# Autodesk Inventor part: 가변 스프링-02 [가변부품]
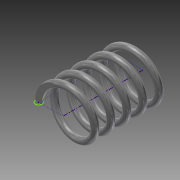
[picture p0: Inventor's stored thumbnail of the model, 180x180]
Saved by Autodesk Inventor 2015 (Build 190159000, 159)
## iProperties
Created: 2015-05
Part Number: 가변 스프링-02 [가변부품]
Material: 강철, 탄소
Document SubType Name: Modeling
Designer: Young-Hwan
Density: 7.85 g/cm^3
Appearance: 반연마
Mass: 18.8381 g
Surface Area: 32.5478 cm^2
Volume: 2.39976 cm^3
Author: Young-Hwan
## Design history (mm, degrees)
sketch "스케치1"
  geometry: L1 (0, 0)-(-11, 0); L2 (-11, 0)-(-11, 36.411); L3 (-11, 36.411)-(0, 36.411); L4 (0, 36.411)-(0, 0); C1 r 1.5 at (-11, 0)
  constraints: 8 end point, 2 parallel, 1 centre point, 1 coincident, 1 horizontal, 1 perpendicular
  dimensions: "d0" = 22 diameter of L2 L4; "d1" = 36.4112 distance between parallel lines of L3 L1 (derived); "d2" = 3 diameter of C1 (derived)
feature "코일1" sketch "스케치1" pitch "d3" = 10; turns "d5" = 5; dims "d4" = 36.4112 (= d1), "d6" = 0, angle "d7" = 90 deg, angle "d8" = 90 deg, "d9" = 0, "d10" = 0
sketch "스케치2"
  geometry: L1 (12.5, 0)-(9.5, 0) reference; 1 further point
  constraints: 1 horizontal alignment
extrude "돌출1" cut sketch "스케치2" stored distance "d11" = 10; taper "d12" = 0 deg
node "작업 평면1"
sketch "스케치3"
  geometry: L1 (-1.5, 0)-(1.5, 0) reference; 1 further point
  constraints: 1 horizontal alignment
extrude "돌출2" cut sketch "스케치3" stored distance "d14" = 10; taper "d15" = 0 deg
node "솔리드1"
node "절단 모서리 투영1"
node "절단 모서리 투영2"
other parameters: "d13" = 90 deg
